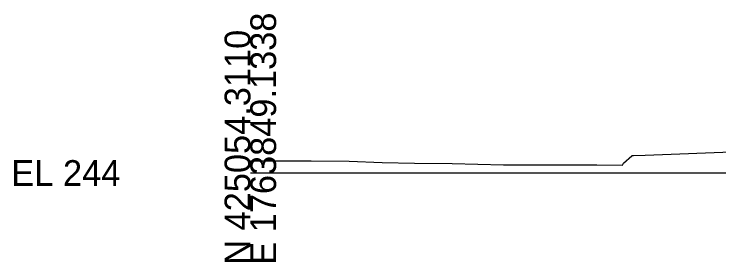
# Model space of a CAD drawing. Extents: x -26 to 3203, y -11010 to 4024.
# Drawn here: x 2974.3 to 3051, y -4009.7 to -3982.7 of the extents above; entities that cross this region are included whole.
import ezdxf

# ---------------------------------------------------------------- set-up
doc = ezdxf.new("R2010")
doc.units = 0
for name, color, linetype in [('Default', 7, 'Continuous'), ('Exist Cross Section Cell', 7, 'Continuous'), ('Exist XS Ground Line', 7, 'Continuous')]:
    doc.layers.add(name, color=color, linetype=linetype)

msp = doc.modelspace()

# ---------------------------------------------------------------- linework, layer by layer
at = {"layer": 'Exist Cross Section Cell'}
msp.add_line((3000, -4000), (3100, -4000), dxfattribs=at)
at = {"layer": 'Exist XS Ground Line'}
msp.add_lwpolyline([(3000, -3998.669), (3001.142, -3998.661), (3006.612, -3998.68), (3010.762, -3998.723), (3014.33, -3998.852), (3017.853, -3998.924), (3021.951, -3998.962), (3027.518, -3999.098), (3037.661, -3999.118), (3040.459, -3999.148), (3040.523, -3999.086), (3040.57, -3998.922), (3041.498, -3998.116), (3041.529, -3998.103), (3041.53, -3998.103), (3041.655, -3998.098), (3042.94, -3998.046), (3053.27, -3997.641)], dxfattribs=at)
msp.add_lwpolyline([(3000, -3998.669), (3001.142, -3998.661), (3006.612, -3998.68), (3010.762, -3998.723), (3014.33, -3998.852), (3017.853, -3998.924), (3021.951, -3998.962), (3027.518, -3999.098), (3037.661, -3999.118), (3040.459, -3999.148), (3040.523, -3999.086), (3040.57, -3998.922), (3041.498, -3998.116), (3041.529, -3998.103), (3041.53, -3998.103), (3041.655, -3998.098), (3042.94, -3998.046), (3053.27, -3997.641)], dxfattribs=at)
msp.add_lwpolyline([(3000, -3998.669), (3001.142, -3998.661), (3006.612, -3998.68), (3010.762, -3998.723), (3014.33, -3998.852), (3017.853, -3998.924), (3021.951, -3998.962), (3027.518, -3999.098), (3037.661, -3999.118), (3040.459, -3999.148), (3040.523, -3999.086), (3040.57, -3998.922), (3041.498, -3998.116), (3041.529, -3998.103), (3041.53, -3998.103), (3041.655, -3998.098), (3042.94, -3998.046), (3053.27, -3997.641)], dxfattribs=at)
msp.add_lwpolyline([(3000, -3998.669), (3001.142, -3998.661), (3006.612, -3998.68), (3010.762, -3998.723), (3014.33, -3998.852), (3017.853, -3998.924), (3021.951, -3998.962), (3027.518, -3999.098), (3037.661, -3999.118), (3040.459, -3999.148), (3040.523, -3999.086), (3040.57, -3998.922), (3041.498, -3998.116), (3041.529, -3998.103), (3041.53, -3998.103), (3041.655, -3998.098), (3042.94, -3998.046), (3053.27, -3997.641)], dxfattribs=at)
msp.add_lwpolyline([(3000, -3998.669), (3001.142, -3998.661), (3006.612, -3998.68), (3010.762, -3998.723), (3014.33, -3998.852), (3017.853, -3998.924), (3021.951, -3998.962), (3027.518, -3999.098), (3037.661, -3999.118), (3040.459, -3999.148), (3040.523, -3999.086), (3040.57, -3998.922), (3041.498, -3998.116), (3041.529, -3998.103), (3041.53, -3998.103), (3041.655, -3998.098), (3042.94, -3998.046), (3053.27, -3997.641)], dxfattribs=at)

# ---------------------------------------------------------------- texts
at = {"layer": 'Default'}
msp.add_text('-', height=0.0001, dxfattribs=at).set_placement((3000, -4000))
at = {"layer": 'Exist Cross Section Cell'}
for s, p in [('E 1763849.1338', (3002.8, -4010)), ('N 425054.3110', (3000, -4010))]:
    msp.add_text(s, height=2.8, rotation=90, dxfattribs=at).set_placement(p)
msp.add_text('EL 244', height=2.8, dxfattribs=at).set_placement((2974, -4001.4))

doc.saveas('drawing.dxf')
